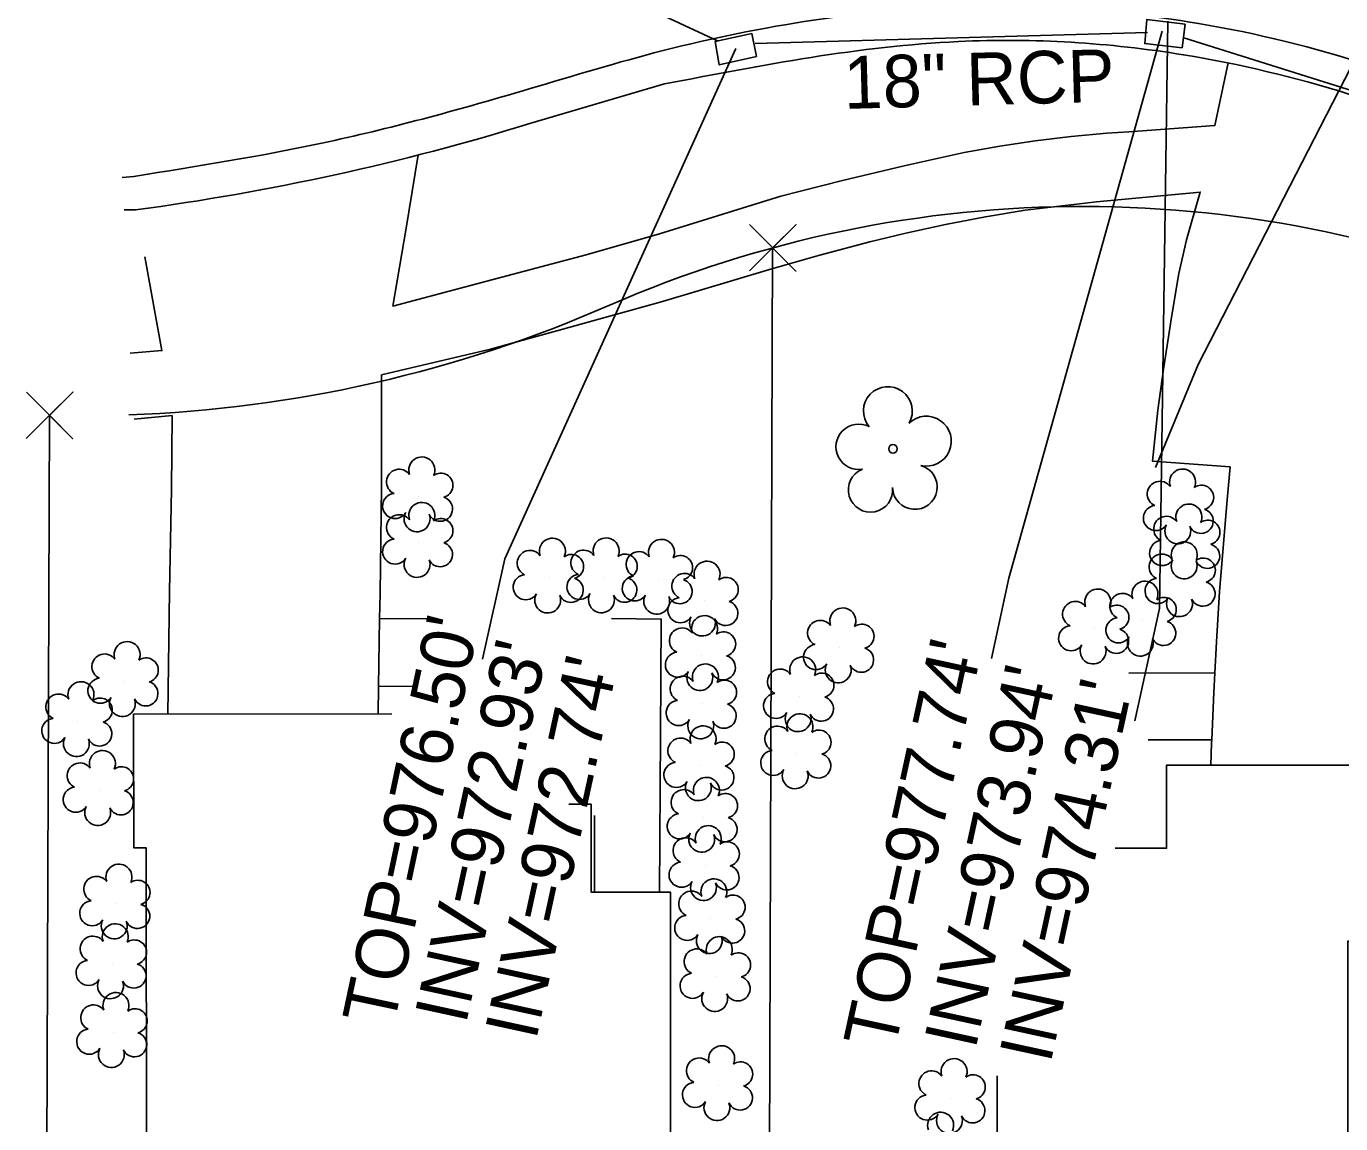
# Model space of a CAD drawing. Extents: x 1611576 to 1617186, y 899279 to 905462.
# Drawn here: x 1616312 to 1616412.1, y 901606.7 to 901690.2 of the extents above; entities that cross this region are included whole.
import ezdxf

# ---------------------------------------------------------------- set-up
doc = ezdxf.new("R2010")
doc.units = 0
for name, color, linetype in [('Exist Building', 7, 'Continuous'), ('Exist Horizontal Alignment', 7, 'Continuous'), ('Exist Other Culture Area Outline', 7, 'Continuous'), ('Exist Property Corner CELL', 7, 'Continuous'), ('Exist Property Line', 7, 'Continuous'), ('Exist Right of Way Line', 7, 'Continuous'), ('Exist Roads Curbs', 7, 'Continuous'), ('Exist Roads EOP', 7, 'Continuous'), ('Exist Roads EOP Other', 7, 'Continuous'), ('Exist Structure Minor Catch Basin', 7, 'Continuous'), ('Exist Structure Minor Catch Basin Leader', 7, 'Continuous'), ('Exist Structure Minor Catch Basin Top Elevation', 7, 'Continuous'), ('Exist Structure Minor Pipes RCP 18 Inch', 7, 'Continuous'), ('Exist Structure Minor Pipes RCP 18 Inch Invert', 7, 'Continuous'), ('Exist Structure Minor Pipes RCP 18 Inch Leader', 7, 'Continuous'), ('Exist Structure Minor Pipes RCP 18 Inch Text', 7, 'Continuous'), ('Exist Vegetation Shrub CELL', 7, 'Continuous'), ('Exist Vegetation Tree CELL', 7, 'Continuous'), ('Prop UG Pow Cables', 7, 'Continuous')]:
    doc.layers.add(name, color=color, linetype=linetype)

msp = doc.modelspace()

# ---------------------------------------------------------------- linework, layer by layer
at = {"layer": 'Exist Building'}
for points in [[(1616353.33, 901631), (1616355.02, 901631), (1616355.03, 901624.3), (1616361.06, 901624.31), (1616361.1, 901580.72), (1616321.2, 901580.68), (1616321.15, 901627.69), (1616320.21, 901627.69), (1616320.2, 901637.85), (1616339.86, 901637.87)], [(1616394.9, 901627.65), (1616398.83, 901627.65), (1616398.83, 901633.97), (1616413.52, 901633.97), (1616413.52, 901620.57), (1616412.61, 901620.57), (1616412.61, 901591.7), (1616385.93, 901591.7), (1616385.93, 901610.33)]]:
    msp.add_lwpolyline(points, dxfattribs=at)
at = {"layer": 'Exist Horizontal Alignment'}
msp.add_arc((1616560.48, 901967.64), 301.56, 239.9333, 268.5167, dxfattribs=at)
at = {"layer": 'Exist Other Culture Area Outline'}
for points in [[(1616342.96, 901645.12), (1616338.93, 901645.11)], [(1616360.23, 901624.31), (1616360.31, 901636.27), (1616360.36, 901645.08), (1616356.58, 901645.12)], [(1616402.5, 901640.97), (1616395.96, 901640.99)], [(1616341.48, 901639.98), (1616338.85, 901639.96)], [(1616402.26, 901635.9), (1616397.42, 901635.89)], [(1616355.29, 901624.3), (1616355.28, 901630.14)]]:
    msp.add_lwpolyline(points, dxfattribs=at)
at = {"layer": 'Exist Property Corner CELL'}
for p, q in [((1616368.84, 901673.34), (1616368.84, 901673.34)), ((1616313.81, 901660.59), (1616313.81, 901660.59))]:
    msp.add_line(p, q, dxfattribs=at)
for points in [[(1616367.08, 901675.11), (1616370.61, 901671.56), (1616368.84, 901673.34), (1616370.62, 901675.1), (1616367.07, 901671.57)], [(1616312.05, 901662.36), (1616315.57, 901658.81), (1616313.81, 901660.59), (1616315.59, 901662.35), (1616312.04, 901658.83)]]:
    msp.add_lwpolyline(points, dxfattribs=at)
at = {"layer": 'Exist Property Line'}
for p, q in [((1616368.84, 901673.34), (1616368.22, 901497.02)), ((1616313.81, 901660.59), (1616313.23, 901497.17))]:
    msp.add_line(p, q, dxfattribs=at)
at = {"layer": 'Exist Right of Way Line'}
for centre, radius, start, end in [((1616392.44, 901586.48), 90, 66.2087, 113.6264), ((1616316.3, 901760.56), 100, 272.0309, 293.6264)]:
    msp.add_arc(centre, radius, start, end, dxfattribs=at)
at = {"layer": 'Exist Roads Curbs'}
for p, q in [((1616360.61, 901685.8), (1616350.44, 901682.81)), ((1616320.36, 901676.22), (1616319.49, 901676.22))]:
    msp.add_line(p, q, dxfattribs=at)
msp.add_ellipse((1616295.62, 901859.17), major_axis=(184.06, -21.03), ratio=0.996311, start_param=4.959683, end_param=5.126158, dxfattribs=at)
for points in [[(1616499.21, 901686.1), (1616458.12, 901698.74), (1616435.43, 901711.26), (1616421.11, 901726.34), (1616409.38, 901744.29), (1616402.27, 901762.22), (1616399.82, 901773.89)], [(1616426.53, 901679.99), (1616412.78, 901685.01), (1616400.12, 901688.02), (1616382.99, 901689.03), (1616360.61, 901685.8)]]:
    msp.add_spline(points, degree=3, dxfattribs=at)
at = {"layer": 'Exist Roads EOP'}
msp.add_line((1616320.23, 901678.77), (1616319.34, 901678.69), dxfattribs=at)
for points in [[(1616498.76, 901683.66), (1616457.12, 901696.41), (1616433.94, 901709.32), (1616419.26, 901724.86), (1616407.16, 901743.23), (1616399.81, 901761.54), (1616397.32, 901773.43)], [(1616600.7, 901615.07), (1616596.49, 901640.71), (1616577.82, 901651.88), (1616577.76, 901653.58), (1616560.38, 901654.4), (1616541.66, 901655.74), (1616514.62, 901658.97), (1616481.57, 901665.46), (1616453.29, 901673.28), (1616429.01, 901681.85), (1616427.56, 901682.36), (1616413.54, 901687.44), (1616400.43, 901690.54), (1616382.85, 901691.64), (1616359.81, 901688.16), (1616349.76, 901685.26), (1616334.54, 901681.3), (1616320.23, 901678.77)]]:
    msp.add_spline(points, degree=3, dxfattribs=at)
at = {"layer": 'Exist Roads EOP Other'}
for points in [[(1616341.87, 901680.42), (1616340.94, 901674.83), (1616339.93, 901668.9), (1616348.23, 901671.1), (1616354.66, 901672.79), (1616360.22, 901674.4), (1616369.47, 901677.26), (1616374.15, 901678.45), (1616378.86, 901679.57), (1616383.43, 901680.58), (1616386.13, 901681.06), (1616388.83, 901681.47), (1616391.55, 901681.8), (1616394.28, 901682.05), (1616395.95, 901682.16), (1616402.49, 901682.64), (1616403.5, 901687.4)], [(1616399.2, 901668.05), (1616399.76, 901671.38), (1616400.34, 901673.95), (1616401.39, 901677.58), (1616393.5, 901676.84), (1616388.07, 901676.2), (1616385.03, 901675.7), (1616382, 901675.12), (1616378.99, 901674.46), (1616376.23, 901673.79), (1616372.34, 901672.76), (1616368.59, 901671.68), (1616360.47, 901669.25), (1616352.87, 901667.15), (1616347.37, 901665.61), (1616339.08, 901663.67)], [(1616319.94, 901665.31), (1616322.36, 901665.51), (1616321.06, 901672.64)], [(1616402.19, 901633.97), (1616402.25, 901635.65), (1616402.26, 901635.9), (1616402.42, 901639.5), (1616402.5, 901640.97), (1616402.62, 901643.35), (1616402.86, 901647.19), (1616402.92, 901648.1), (1616403.44, 901654.16), (1616403.66, 901656.66), (1616397.74, 901657.11), (1616398.16, 901660.97), (1616398.58, 901664.1), (1616399.06, 901667.21), (1616399.2, 901668.05)], [(1616338.81, 901637.86), (1616338.85, 901639.96), (1616338.93, 901645.11), (1616338.96, 901647.04), (1616339.07, 901655.18), (1616339.08, 901663.67)], [(1616322.82, 901637.85), (1616322.94, 901647.21), (1616323.08, 901654.96), (1616323.13, 901660.57), (1616320.26, 901660.3)]]:
    msp.add_lwpolyline(points, dxfattribs=at)
at = {"layer": 'Exist Structure Minor Catch Basin'}
for points in [[(1616400.02, 901688.54), (1616400.23, 901690.34), (1616397.33, 901690.71), (1616397.16, 901688.87), (1616400.02, 901688.54)], [(1616367.62, 901687.88), (1616367.27, 901689.63), (1616364.46, 901689.02), (1616364.78, 901687.25), (1616367.62, 901687.88)]]:
    msp.add_lwpolyline(points, dxfattribs=at)
at = {"layer": 'Exist Structure Minor Catch Basin Leader'}
msp.add_lwpolyline([(1616366.03, 901688.51), (1616348.46, 901649.68), (1616346.76, 901642.04)], dxfattribs=at)
at = {"layer": 'Exist Structure Minor Pipes RCP 18 Inch'}
for p, q in [((1616343.13, 901699.14), (1616364.64, 901689.08)), ((1616343.13, 901699.14), (1616364.64, 901689.08)), ((1616367.5, 901688.89), (1616397.37, 901689.71)), ((1616367.5, 901688.89), (1616397.37, 901689.71)), ((1616400.14, 901689.31), (1616478.43, 901664.67)), ((1616400.14, 901689.31), (1616478.43, 901664.67))]:
    msp.add_line(p, q, dxfattribs=at)
at = {"layer": 'Exist Structure Minor Pipes RCP 18 Inch Leader'}
for points in [[(1616398.91, 901690.57), (1616398.28, 901645.89), (1616396.4, 901637.33)], [(1616398.5, 901689.81), (1616386.82, 901648.2), (1616385.5, 901642.08)]]:
    msp.add_lwpolyline(points, dxfattribs=at)
at = {"layer": 'Exist Vegetation Shrub CELL'}
for p, q in [((1616341.91, 901654.39), (1616341.91, 901654.39)), ((1616399.81, 901653.47), (1616399.81, 901653.47)), ((1616341.91, 901650.93), (1616341.91, 901650.93)), ((1616400.29, 901650.81), (1616400.29, 901650.81)), ((1616351.85, 901648.21), (1616351.85, 901648.21)), ((1616355.94, 901648.23), (1616355.94, 901648.23)), ((1616360.15, 901648.12), (1616360.15, 901648.12)), ((1616399.94, 901647.93), (1616399.94, 901647.93)), ((1616363.62, 901646.46), (1616363.62, 901646.46)), ((1616396.96, 901644.94), (1616396.96, 901644.94)), ((1616393.36, 901644.34), (1616393.36, 901644.34)), ((1616373.96, 901642.9), (1616373.96, 901642.9)), ((1616363.43, 901642.32), (1616363.43, 901642.32)), ((1616319.48, 901640.34), (1616319.48, 901640.34)), ((1616363.49, 901638.64), (1616363.49, 901638.64)), ((1616370.9, 901639.18), (1616370.9, 901639.18)), ((1616315.97, 901637.29), (1616315.97, 901637.29)), ((1616370.69, 901634.84), (1616370.69, 901634.84)), ((1616363.32, 901633.93), (1616363.32, 901633.93)), ((1616317.6, 901632.05), (1616317.6, 901632.05)), ((1616363.57, 901630.01), (1616363.57, 901630.01)), ((1616363.71, 901626.34), (1616363.71, 901626.34)), ((1616318.86, 901623.41), (1616318.86, 901623.41)), ((1616364.14, 901622.29), (1616364.14, 901622.29)), ((1616318.58, 901618.87), (1616318.58, 901618.87)), ((1616364.55, 901617.89), (1616364.55, 901617.89)), ((1616318.64, 901613.64), (1616318.64, 901613.64)), ((1616364.73, 901609.59), (1616364.73, 901609.59)), ((1616382.42, 901608.61), (1616382.42, 901608.61))]:
    msp.add_line(p, q, dxfattribs=at)
for centre, radius, start, end in [((1616340.42, 901655.52), 0.968, 35.8908, 245.4216), ((1616342.14, 901656.43), 0.99, 334.8391, 200.4717), ((1616400.04, 901655.51), 0.99, 334.8391, 200.4717), ((1616343.58, 901655.26), 0.929, 284.4567, 126.0861), ((1616398.32, 901654.6), 0.968, 35.8908, 245.4216), ((1616340.11, 901653.69), 0.955, 95.1099, 327.9534), ((1616401.48, 901654.34), 0.929, 284.4567, 126.0861), ((1616342.14, 901652.97), 0.99, 334.8391, 200.4717), ((1616343.54, 901653.46), 0.937, 204.9913, 73.4601), ((1616398.01, 901652.77), 0.955, 95.1099, 327.9534), ((1616400.52, 901652.85), 0.99, 334.8391, 200.4717), ((1616340.42, 901652.06), 0.968, 35.8908, 245.4216), ((1616341.78, 901652.71), 0.984, 151.2797, 21.387), ((1616343.58, 901651.8), 0.929, 284.4567, 126.0861), ((1616398.81, 901651.94), 0.968, 35.8908, 245.4216), ((1616401.44, 901652.54), 0.937, 204.9913, 73.4601), ((1616401.96, 901651.68), 0.929, 284.4567, 126.0861), ((1616399.68, 901651.79), 0.984, 151.2797, 21.387), ((1616340.11, 901650.22), 0.955, 95.1099, 327.9534), ((1616343.54, 901650), 0.937, 204.9913, 73.4601), ((1616352.08, 901650.25), 0.99, 334.8391, 200.4717), ((1616356.17, 901650.27), 0.99, 334.8391, 200.4717), ((1616360.38, 901650.16), 0.99, 334.8391, 200.4717), ((1616398.49, 901650.11), 0.955, 95.1099, 327.9534), ((1616400.17, 901649.97), 0.99, 334.8391, 200.4717), ((1616401.93, 901649.88), 0.937, 204.9913, 73.4601), ((1616341.78, 901649.24), 0.984, 151.2797, 21.387), ((1616350.37, 901649.34), 0.968, 35.8908, 245.4216), ((1616353.52, 901649.08), 0.929, 284.4567, 126.0861), ((1616354.45, 901649.36), 0.968, 35.8908, 245.4216), ((1616357.61, 901649.1), 0.929, 284.4567, 126.0861), ((1616358.66, 901649.25), 0.968, 35.8908, 245.4216), ((1616361.82, 901648.99), 0.929, 284.4567, 126.0861), ((1616363.85, 901648.5), 0.99, 334.8391, 200.4717), ((1616398.46, 901649.06), 0.968, 35.8908, 245.4216), ((1616400.16, 901649.13), 0.984, 151.2797, 21.387), ((1616401.61, 901648.8), 0.929, 284.4567, 126.0861), ((1616354.14, 901647.53), 0.955, 95.1099, 327.9534), ((1616362.14, 901647.59), 0.968, 35.8908, 245.4216), ((1616350.05, 901647.51), 0.955, 95.1099, 327.9534), ((1616353.49, 901647.29), 0.937, 204.9913, 73.4601), ((1616357.57, 901647.3), 0.937, 204.9913, 73.4601), ((1616358.35, 901647.42), 0.955, 95.1099, 327.9534), ((1616361.78, 901647.19), 0.937, 204.9913, 73.4601), ((1616365.3, 901647.33), 0.929, 284.4567, 126.0861), ((1616397.18, 901646.98), 0.99, 334.8391, 200.4717), ((1616398.14, 901647.22), 0.955, 95.1099, 327.9534), ((1616401.58, 901647), 0.937, 204.9913, 73.4601), ((1616351.72, 901646.53), 0.984, 151.2797, 21.387), ((1616355.81, 901646.55), 0.984, 151.2797, 21.387), ((1616360.02, 901646.44), 0.984, 151.2797, 21.387), ((1616361.82, 901645.76), 0.955, 95.1099, 327.9534), ((1616393.59, 901646.38), 0.99, 334.8391, 200.4717), ((1616395.47, 901646.07), 0.968, 35.8908, 245.4216), ((1616398.63, 901645.81), 0.929, 284.4567, 126.0861), ((1616399.81, 901646.25), 0.984, 151.2797, 21.387), ((1616365.26, 901645.53), 0.937, 204.9913, 73.4601), ((1616374.18, 901644.94), 0.99, 334.8391, 200.4717), ((1616391.88, 901645.46), 0.968, 35.8908, 245.4216), ((1616395.03, 901645.21), 0.929, 284.4567, 126.0861), ((1616363.5, 901644.78), 0.984, 151.2797, 21.387), ((1616363.66, 901644.36), 0.99, 334.8391, 200.4717), ((1616372.47, 901644.02), 0.968, 35.8908, 245.4216), ((1616375.63, 901643.77), 0.929, 284.4567, 126.0861), ((1616391.56, 901643.63), 0.955, 95.1099, 327.9534), ((1616395.16, 901644.23), 0.955, 95.1099, 327.9534), ((1616398.59, 901644.01), 0.937, 204.9913, 73.4601), ((1616361.95, 901643.44), 0.968, 35.8908, 245.4216), ((1616365.1, 901643.18), 0.929, 284.4567, 126.0861), ((1616395, 901643.41), 0.937, 204.9913, 73.4601), ((1616396.83, 901643.25), 0.984, 151.2797, 21.387), ((1616319.71, 901642.38), 0.99, 334.8391, 200.4717), ((1616361.63, 901641.61), 0.955, 95.1099, 327.9534), ((1616372.15, 901642.19), 0.955, 95.1099, 327.9534), ((1616375.59, 901641.97), 0.937, 204.9913, 73.4601), ((1616393.23, 901642.65), 0.984, 151.2797, 21.387), ((1616318, 901641.46), 0.968, 35.8908, 245.4216), ((1616321.15, 901641.2), 0.929, 284.4567, 126.0861), ((1616363.72, 901640.68), 0.99, 334.8391, 200.4717), ((1616365.07, 901641.39), 0.937, 204.9913, 73.4601), ((1616371.13, 901641.22), 0.99, 334.8391, 200.4717), ((1616373.83, 901641.21), 0.984, 151.2797, 21.387), ((1616317.68, 901639.63), 0.955, 95.1099, 327.9534), ((1616362.01, 901639.77), 0.968, 35.8908, 245.4216), ((1616363.3, 901640.63), 0.984, 151.2797, 21.387), ((1616369.42, 901640.31), 0.968, 35.8908, 245.4216), ((1616372.58, 901640.05), 0.929, 284.4567, 126.0861), ((1616316.2, 901639.33), 0.99, 334.8391, 200.4717), ((1616321.12, 901639.41), 0.937, 204.9913, 73.4601), ((1616365.17, 901639.51), 0.929, 284.4567, 126.0861), ((1616314.49, 901638.41), 0.968, 35.8908, 245.4216), ((1616317.65, 901638.15), 0.929, 284.4567, 126.0861), ((1616319.35, 901638.65), 0.984, 151.2797, 21.387), ((1616361.69, 901637.94), 0.955, 95.1099, 327.9534), ((1616365.13, 901637.71), 0.937, 204.9913, 73.4601), ((1616369.1, 901638.48), 0.955, 95.1099, 327.9534), ((1616372.54, 901638.25), 0.937, 204.9913, 73.4601), ((1616314.17, 901636.58), 0.955, 95.1099, 327.9534), ((1616370.78, 901637.5), 0.984, 151.2797, 21.387), ((1616370.92, 901636.89), 0.99, 334.8391, 200.4717), ((1616317.61, 901636.36), 0.937, 204.9913, 73.4601), ((1616363.37, 901636.96), 0.984, 151.2797, 21.387), ((1616363.55, 901635.97), 0.99, 334.8391, 200.4717), ((1616369.21, 901635.97), 0.968, 35.8908, 245.4216), ((1616372.36, 901635.71), 0.929, 284.4567, 126.0861), ((1616315.85, 901635.6), 0.984, 151.2797, 21.387), ((1616361.84, 901635.06), 0.968, 35.8908, 245.4216), ((1616364.99, 901634.8), 0.929, 284.4567, 126.0861), ((1616317.83, 901634.09), 0.99, 334.8391, 200.4717), ((1616368.89, 901634.14), 0.955, 95.1099, 327.9534), ((1616372.33, 901633.92), 0.937, 204.9913, 73.4601), ((1616316.12, 901633.17), 0.968, 35.8908, 245.4216), ((1616319.28, 901632.92), 0.929, 284.4567, 126.0861), ((1616361.52, 901633.23), 0.955, 95.1099, 327.9534), ((1616364.96, 901633.01), 0.937, 204.9913, 73.4601), ((1616370.56, 901633.16), 0.984, 151.2797, 21.387), ((1616363.19, 901632.25), 0.984, 151.2797, 21.387), ((1616363.8, 901632.05), 0.99, 334.8391, 200.4717), ((1616315.8, 901631.34), 0.955, 95.1099, 327.9534), ((1616319.24, 901631.12), 0.937, 204.9913, 73.4601), ((1616362.08, 901631.14), 0.968, 35.8908, 245.4216), ((1616365.24, 901630.88), 0.929, 284.4567, 126.0861), ((1616317.47, 901630.36), 0.984, 151.2797, 21.387), ((1616361.77, 901629.31), 0.955, 95.1099, 327.9534), ((1616365.2, 901629.08), 0.937, 204.9913, 73.4601), ((1616363.44, 901628.33), 0.984, 151.2797, 21.387), ((1616363.94, 901628.38), 0.99, 334.8391, 200.4717), ((1616362.23, 901627.47), 0.968, 35.8908, 245.4216), ((1616365.38, 901627.21), 0.929, 284.4567, 126.0861), ((1616361.91, 901625.63), 0.955, 95.1099, 327.9534), ((1616317.38, 901624.54), 0.968, 35.8908, 245.4216), ((1616319.09, 901625.45), 0.99, 334.8391, 200.4717), ((1616365.35, 901625.41), 0.937, 204.9913, 73.4601), ((1616320.53, 901624.28), 0.929, 284.4567, 126.0861), ((1616363.58, 901624.65), 0.984, 151.2797, 21.387), ((1616364.37, 901624.33), 0.99, 334.8391, 200.4717), ((1616317.06, 901622.7), 0.955, 95.1099, 327.9534), ((1616362.66, 901623.42), 0.968, 35.8908, 245.4216), ((1616365.82, 901623.16), 0.929, 284.4567, 126.0861), ((1616320.5, 901622.48), 0.937, 204.9913, 73.4601), ((1616362.34, 901621.59), 0.955, 95.1099, 327.9534), ((1616318.73, 901621.73), 0.984, 151.2797, 21.387), ((1616318.81, 901620.91), 0.99, 334.8391, 200.4717), ((1616365.78, 901621.36), 0.937, 204.9913, 73.4601), ((1616317.1, 901619.99), 0.968, 35.8908, 245.4216), ((1616320.26, 901619.74), 0.929, 284.4567, 126.0861), ((1616364.02, 901620.61), 0.984, 151.2797, 21.387), ((1616364.78, 901619.93), 0.99, 334.8391, 200.4717), ((1616363.07, 901619.02), 0.968, 35.8908, 245.4216), ((1616366.23, 901618.76), 0.929, 284.4567, 126.0861), ((1616316.78, 901618.16), 0.955, 95.1099, 327.9534), ((1616320.22, 901617.94), 0.937, 204.9913, 73.4601), ((1616318.45, 901617.18), 0.984, 151.2797, 21.387), ((1616362.75, 901617.18), 0.955, 95.1099, 327.9534), ((1616366.19, 901616.96), 0.937, 204.9913, 73.4601), ((1616318.86, 901615.68), 0.99, 334.8391, 200.4717), ((1616364.43, 901616.21), 0.984, 151.2797, 21.387), ((1616317.15, 901614.76), 0.968, 35.8908, 245.4216), ((1616320.31, 901614.51), 0.929, 284.4567, 126.0861), ((1616316.83, 901612.93), 0.955, 95.1099, 327.9534), ((1616320.27, 901612.71), 0.937, 204.9913, 73.4601), ((1616364.96, 901611.63), 0.99, 334.8391, 200.4717), ((1616318.51, 901611.95), 0.984, 151.2797, 21.387), ((1616363.25, 901610.72), 0.968, 35.8908, 245.4216), ((1616382.65, 901610.65), 0.99, 334.8391, 200.4717), ((1616366.4, 901610.46), 0.929, 284.4567, 126.0861), ((1616380.94, 901609.74), 0.968, 35.8908, 245.4216), ((1616362.93, 901608.88), 0.955, 95.1099, 327.9534), ((1616366.37, 901608.66), 0.937, 204.9913, 73.4601), ((1616384.1, 901609.48), 0.929, 284.4567, 126.0861), ((1616380.62, 901607.91), 0.955, 95.1099, 327.9534), ((1616384.06, 901607.68), 0.937, 204.9913, 73.4601), ((1616364.6, 901607.91), 0.984, 151.2797, 21.387), ((1616381.63, 901606.57), 0.99, 334.8391, 200.4717), ((1616382.3, 901606.93), 0.984, 151.2797, 21.387)]:
    msp.add_arc(centre, radius, start, end, dxfattribs=at)
at = {"layer": 'Exist Vegetation Tree CELL'}
msp.add_line((1616378, 901658.03), (1616378, 901658.03), dxfattribs=at)
msp.add_circle((1616378, 901658.03), 0.326, dxfattribs=at)
for centre, radius, start, end in [((1616377.61, 901660.91), 1.86, 330.1651, 219.7134), ((1616380.54, 901658.62), 1.9, 257.1011, 134.1999), ((1616375.39, 901658.19), 1.73, 62.6636, 279.3457), ((1616376.29, 901654.91), 1.69, 111.5671, 6.231), ((1616379.67, 901655.13), 1.7, 181.2822, 74.56)]:
    msp.add_arc(centre, radius, start, end, dxfattribs=at)
at = {"layer": 'Prop UG Pow Cables'}
for p, q in [((1616414.25, 901689.78), (1616401.23, 901664.46)), ((1616401.23, 901664.46), (1616397.99, 901656.61))]:
    msp.add_line(p, q, dxfattribs=at)

# ---------------------------------------------------------------- texts
at = {"layer": 'Exist Structure Minor Catch Basin Top Elevation'}
for s, rotation, p in [("TOP=976.50'", 78.0167, (1616339.99, 901613.98)), ("TOP=977.74'", 77.7167, (1616378.12, 901612.19))]:
    msp.add_text(s, height=4, rotation=rotation, dxfattribs=at).set_placement(p)
at = {"layer": 'Exist Structure Minor Pipes RCP 18 Inch Invert'}
for s, p in [("INV=972.93'", (1616345.49, 901614.16)), ("INV=972.74'", (1616350.83, 901612.95)), ("INV=973.94'", (1616384.27, 901612.25)), ("INV=974.31'", (1616389.98, 901611.18))]:
    msp.add_text(s, height=4, rotation=77.7167, dxfattribs=at).set_placement(p)
at = {"layer": 'Exist Structure Minor Pipes RCP 18 Inch Text'}
msp.add_text('18" RCP', height=4, rotation=1.5723, dxfattribs=at).set_placement((1616374.29, 901683.9))

doc.saveas('drawing.dxf')
